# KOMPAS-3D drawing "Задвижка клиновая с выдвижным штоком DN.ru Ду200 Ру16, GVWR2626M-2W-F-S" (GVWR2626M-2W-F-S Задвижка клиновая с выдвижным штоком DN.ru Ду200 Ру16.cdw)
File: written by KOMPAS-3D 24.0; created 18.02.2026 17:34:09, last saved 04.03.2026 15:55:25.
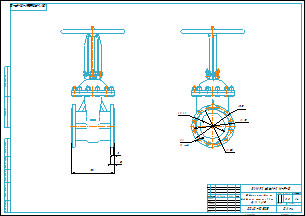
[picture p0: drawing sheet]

Document properties: Автор: R2D2; Форматы листов документа: A2; Полное имя файла: GVWR2626M-2W-F-S Задвижка клиновая с выдвижным штоком DN.ru Ду200 Ру16.m3d; Масса: 108; Наименование: Задвижка клиновая с выдвижным штоком DN.ru Ду200 Ру16; Количество листов документа: 1; Примечание: D040-10505

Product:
- Part/product: Задвижка клиновая с выдвижным штоком DN.ru Ду200 Ру16  | designation GVWR2626M-2W-F-S
    Масса: 108
    Раздел спецификации: Прочие изделия
    Примечание: D040-10505

Referenced files in E:\Работа\Зайцев\Для компаса\: чертеж DN.ru А3.cdt
Referenced files in E:\Работа\Зайцев\GVWR2626M-2W-F-S Задвижка клиновая с выдвижным штоком DN.ru Ду50-300 Ру16\DN200\: GVWR2626M-2W-F-S Задвижка клиновая с выдвижным штоком DN.ru Ду200 Ру16.m3d
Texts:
  чертеж DN.ru А3.cdt
  Задвижка клиновая с
  выдвижным штоком DN.ru
  Ду200 Ру16
  GVWR2626M-2W-F-S
  Задвижка клиновая с выдвижным штоком DN.ru Ду200 Ру16
  GVWR2626M-2W-F-S Задвижка клиновая с выдвижным штоком DN.ru Ду200 Ру16
Dimensions and other numbers on the sheet: 1:4; 0; 1; 2; 108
